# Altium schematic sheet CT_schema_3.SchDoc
size 430 x 414 mm
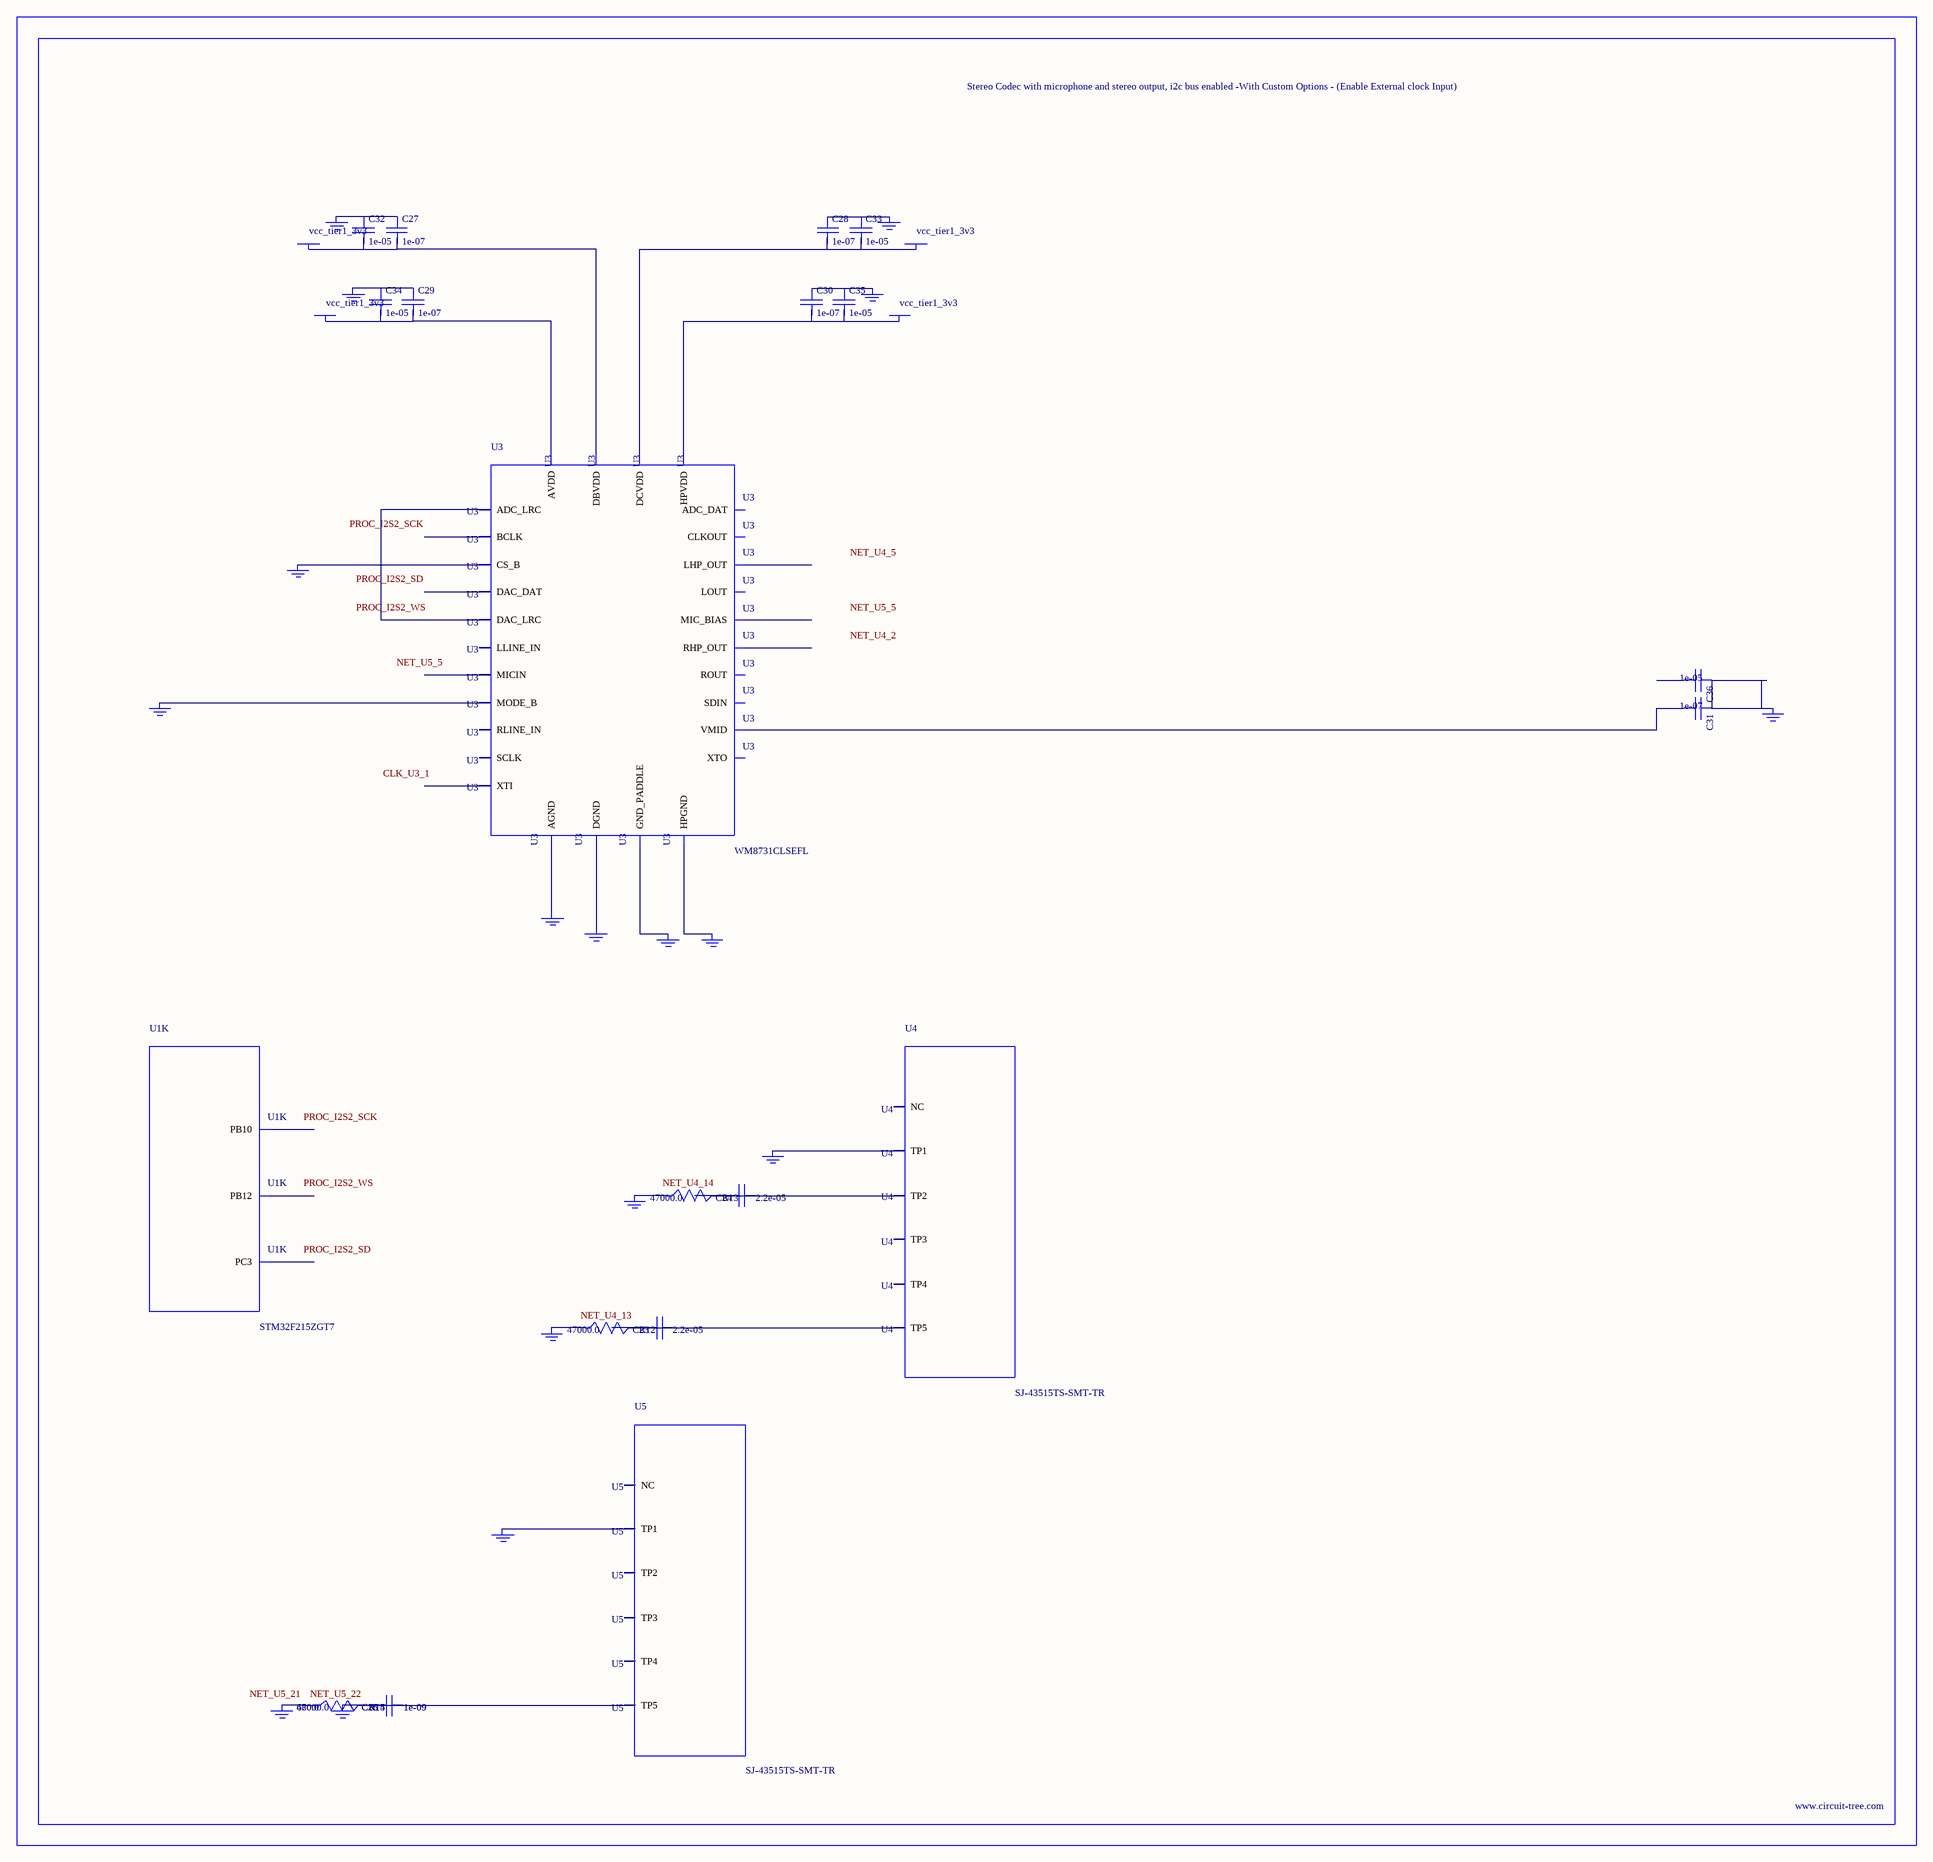
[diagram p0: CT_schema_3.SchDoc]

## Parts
BORDER2  (no value)
C23  2.2e-05  [C1210]
C24  2.2e-05  [C1210]
C25  1e-09  [C0402]
C26  1e-09  [C0402]
C27  1e-07  [C0402]
C28  1e-07  [C0402]
C29  1e-07  [C0402]
C30  1e-07  [C0402]
C31  1e-07  [C0402]
C32  1e-05  [C0805]
C33  1e-05  [C0805]
C34  1e-05  [C0805]
C35  1e-05  [C0805]
C36  1e-05  [C0805]
GND_INSTANCE_2_0  (no value)
GND_INSTANCE_2_1  (no value)
GND_INSTANCE_2_2  (no value)
GND_INSTANCE_2_3  (no value)
GND_INSTANCE_2_4  (no value)
GND_INSTANCE_2_5  (no value)
GND_INSTANCE_2_6  (no value)
GND_INSTANCE_2_7  (no value)
GND_INSTANCE_2_8  (no value)
GND_INSTANCE_2_9  (no value)
GND_INSTANCE_2_10  (no value)
GND_INSTANCE_2_11  (no value)
GND_INSTANCE_2_12  (no value)
GND_INSTANCE_2_13  (no value)
GND_INSTANCE_2_14  (no value)
GND_INSTANCE_2_15  (no value)
GND_INSTANCE_2_16  (no value)
POWER_INSTANCE_2_0  vcc_tier1_3v3
POWER_INSTANCE_2_1  vcc_tier1_3v3
POWER_INSTANCE_2_2  vcc_tier1_3v3
POWER_INSTANCE_2_3  vcc_tier1_3v3
R12  47000.0  [R0603]
R13  47000.0  [R0603]
R14  47000.0  [R0603]
R15  680.0  [R0603]
U1  STM32F215ZGT7  [LQFP144]  (part K of 11)
U3  WM8731CLSEFL  [QFN-28]
U4  SJ-43515TS-SMT-TR  [SJ-43515TS-SMT-TR]
U5  SJ-43515TS-SMT-TR  [SJ-43515TS-SMT-TR]

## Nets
NetC23_1: C23.1 C23.2 R12.2 U4.5(TP5)
NetC24_1: C24.1 C24.2 R13.2 U4.2(TP2)
NetC25_1: C25.1 C25.2 C26.1 C26.2 GND_INSTANCE_2_16.0(GND) R14.2 R15.2 U5.5(TP5)
NetC27_1: C27.1 C32.1 GND_INSTANCE_2_1.0(GND)
NetC27_2: C27.2 C32.2 POWER_INSTANCE_2_1.0(PWR) U3.5(DBVDD)
NetC28_1: C28.1 C33.1 GND_INSTANCE_2_0.0(GND)
NetC28_2: C28.2 C33.2 POWER_INSTANCE_2_0.0(PWR) U3.3(DCVDD)
NetC29_1: C29.1 C34.1 GND_INSTANCE_2_4.0(GND)
NetC29_2: C29.2 C34.2 POWER_INSTANCE_2_3.0(PWR) U3.18(AVDD)
NetC30_1: C30.1 C35.1 GND_INSTANCE_2_2.0(GND)
NetC30_2: C30.2 C35.2 POWER_INSTANCE_2_2.0(PWR) U3.12(HPVDD)
NetC31_1: C31.1 C36.1 GND_INSTANCE_2_5.0(GND)
NetC31_2: C31.2 U3.20(VMID)
NetGND_INSTANCE_2_3_0: GND_INSTANCE_2_3.0(GND) U3.15(HPGND)
NetGND_INSTANCE_2_6_0: GND_INSTANCE_2_6.0(GND) U3.25(MODE_B)
NetGND_INSTANCE_2_7_0: GND_INSTANCE_2_7.0(GND) U3.26(CS_B)
NetGND_INSTANCE_2_8_0: GND_INSTANCE_2_8.0(GND) U3.29(GND_PADDLE)
NetGND_INSTANCE_2_9_0: GND_INSTANCE_2_9.0(GND) U3.4(DGND)
NetGND_INSTANCE_2_10_0: GND_INSTANCE_2_10.0(GND) U3.19(AGND)
NetGND_INSTANCE_2_11_0: GND_INSTANCE_2_11.0(GND) U4.1(TP1)
NetGND_INSTANCE_2_12_0: GND_INSTANCE_2_12.0(GND) R13.1
NetGND_INSTANCE_2_13_0: GND_INSTANCE_2_13.0(GND) R12.1
NetGND_INSTANCE_2_14_0: GND_INSTANCE_2_14.0(GND) U5.1(TP1)
NetGND_INSTANCE_2_15_0: GND_INSTANCE_2_15.0(GND) R14.1 R15.1
NetU3_9: U3.9(DAC_LRC) U3.11(ADC_LRC)

Not connected (* = marked no-connect by the designer): C36 2; U1 29(PC3) 69(PB10) 73(PB12); U3 1(XTI) 2(XTO) 6(CLKOUT) 7(BCLK) 8(DAC_DAT) 10(ADC_DAT) 13(LHP_OUT) 14(RHP_OUT) 16(LOUT) 17(ROUT) 21(MIC_BIAS) 22(MICIN) 23(RLINE_IN) 24(LLINE_IN) 27(SDIN) 28(SCLK); U4 3(TP3) 4(TP4) 6(NC); U5 2(TP2) 3(TP3) 4(TP4) 6(NC)

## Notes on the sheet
- Labels drawn without touching a wire or pin: CLK_U3_1, NET_U4_2, NET_U4_5, NET_U4_13, NET_U4_14, NET_U5_5, NET_U5_21, NET_U5_22, PROC_I2S2_SCK, PROC_I2S2_SD, PROC_I2S2_WS

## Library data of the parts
BORDER2 = BORDER_PAGE2
C23 C24 = C1210C224K5RACTU
C25 C26 = C0402C102K3RAC
C27-C31 = C0402C104K3RACTU
C32-C36 = C0805C106K8RACTU
GND_INSTANCE_2_0-GND_INSTANCE_2_16 = GND
POWER_INSTANCE_2_0-POWER_INSTANCE_2_3 = PWR
R12-R14 = RC0603JR-0747KL
R15 = RC0603JR-07680RL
